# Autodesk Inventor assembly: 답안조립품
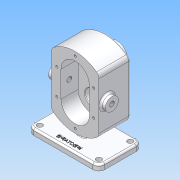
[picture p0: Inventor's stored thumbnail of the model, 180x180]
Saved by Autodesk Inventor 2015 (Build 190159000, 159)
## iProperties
Created: 2019-03
Part Number: 답안조립품
Document SubType Name: Assembly
Designer: user
Author: user
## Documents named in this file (2)
- C:\Users\user\Desktop\490307V1002\답안조립품.iam
- C:\Users\user\Desktop\490307V1002\본체.ipt
